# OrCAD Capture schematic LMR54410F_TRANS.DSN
size D; title: LMR54410F, SIMPLE SWITCHER® 4-V to 36-V,; rev: 1.0; note: Datasheet: SLUSEG8       EVM:SLUUCK7; note: Synchronous Step Down Converter; note: 1-A Buck Converter in SOT-23-6
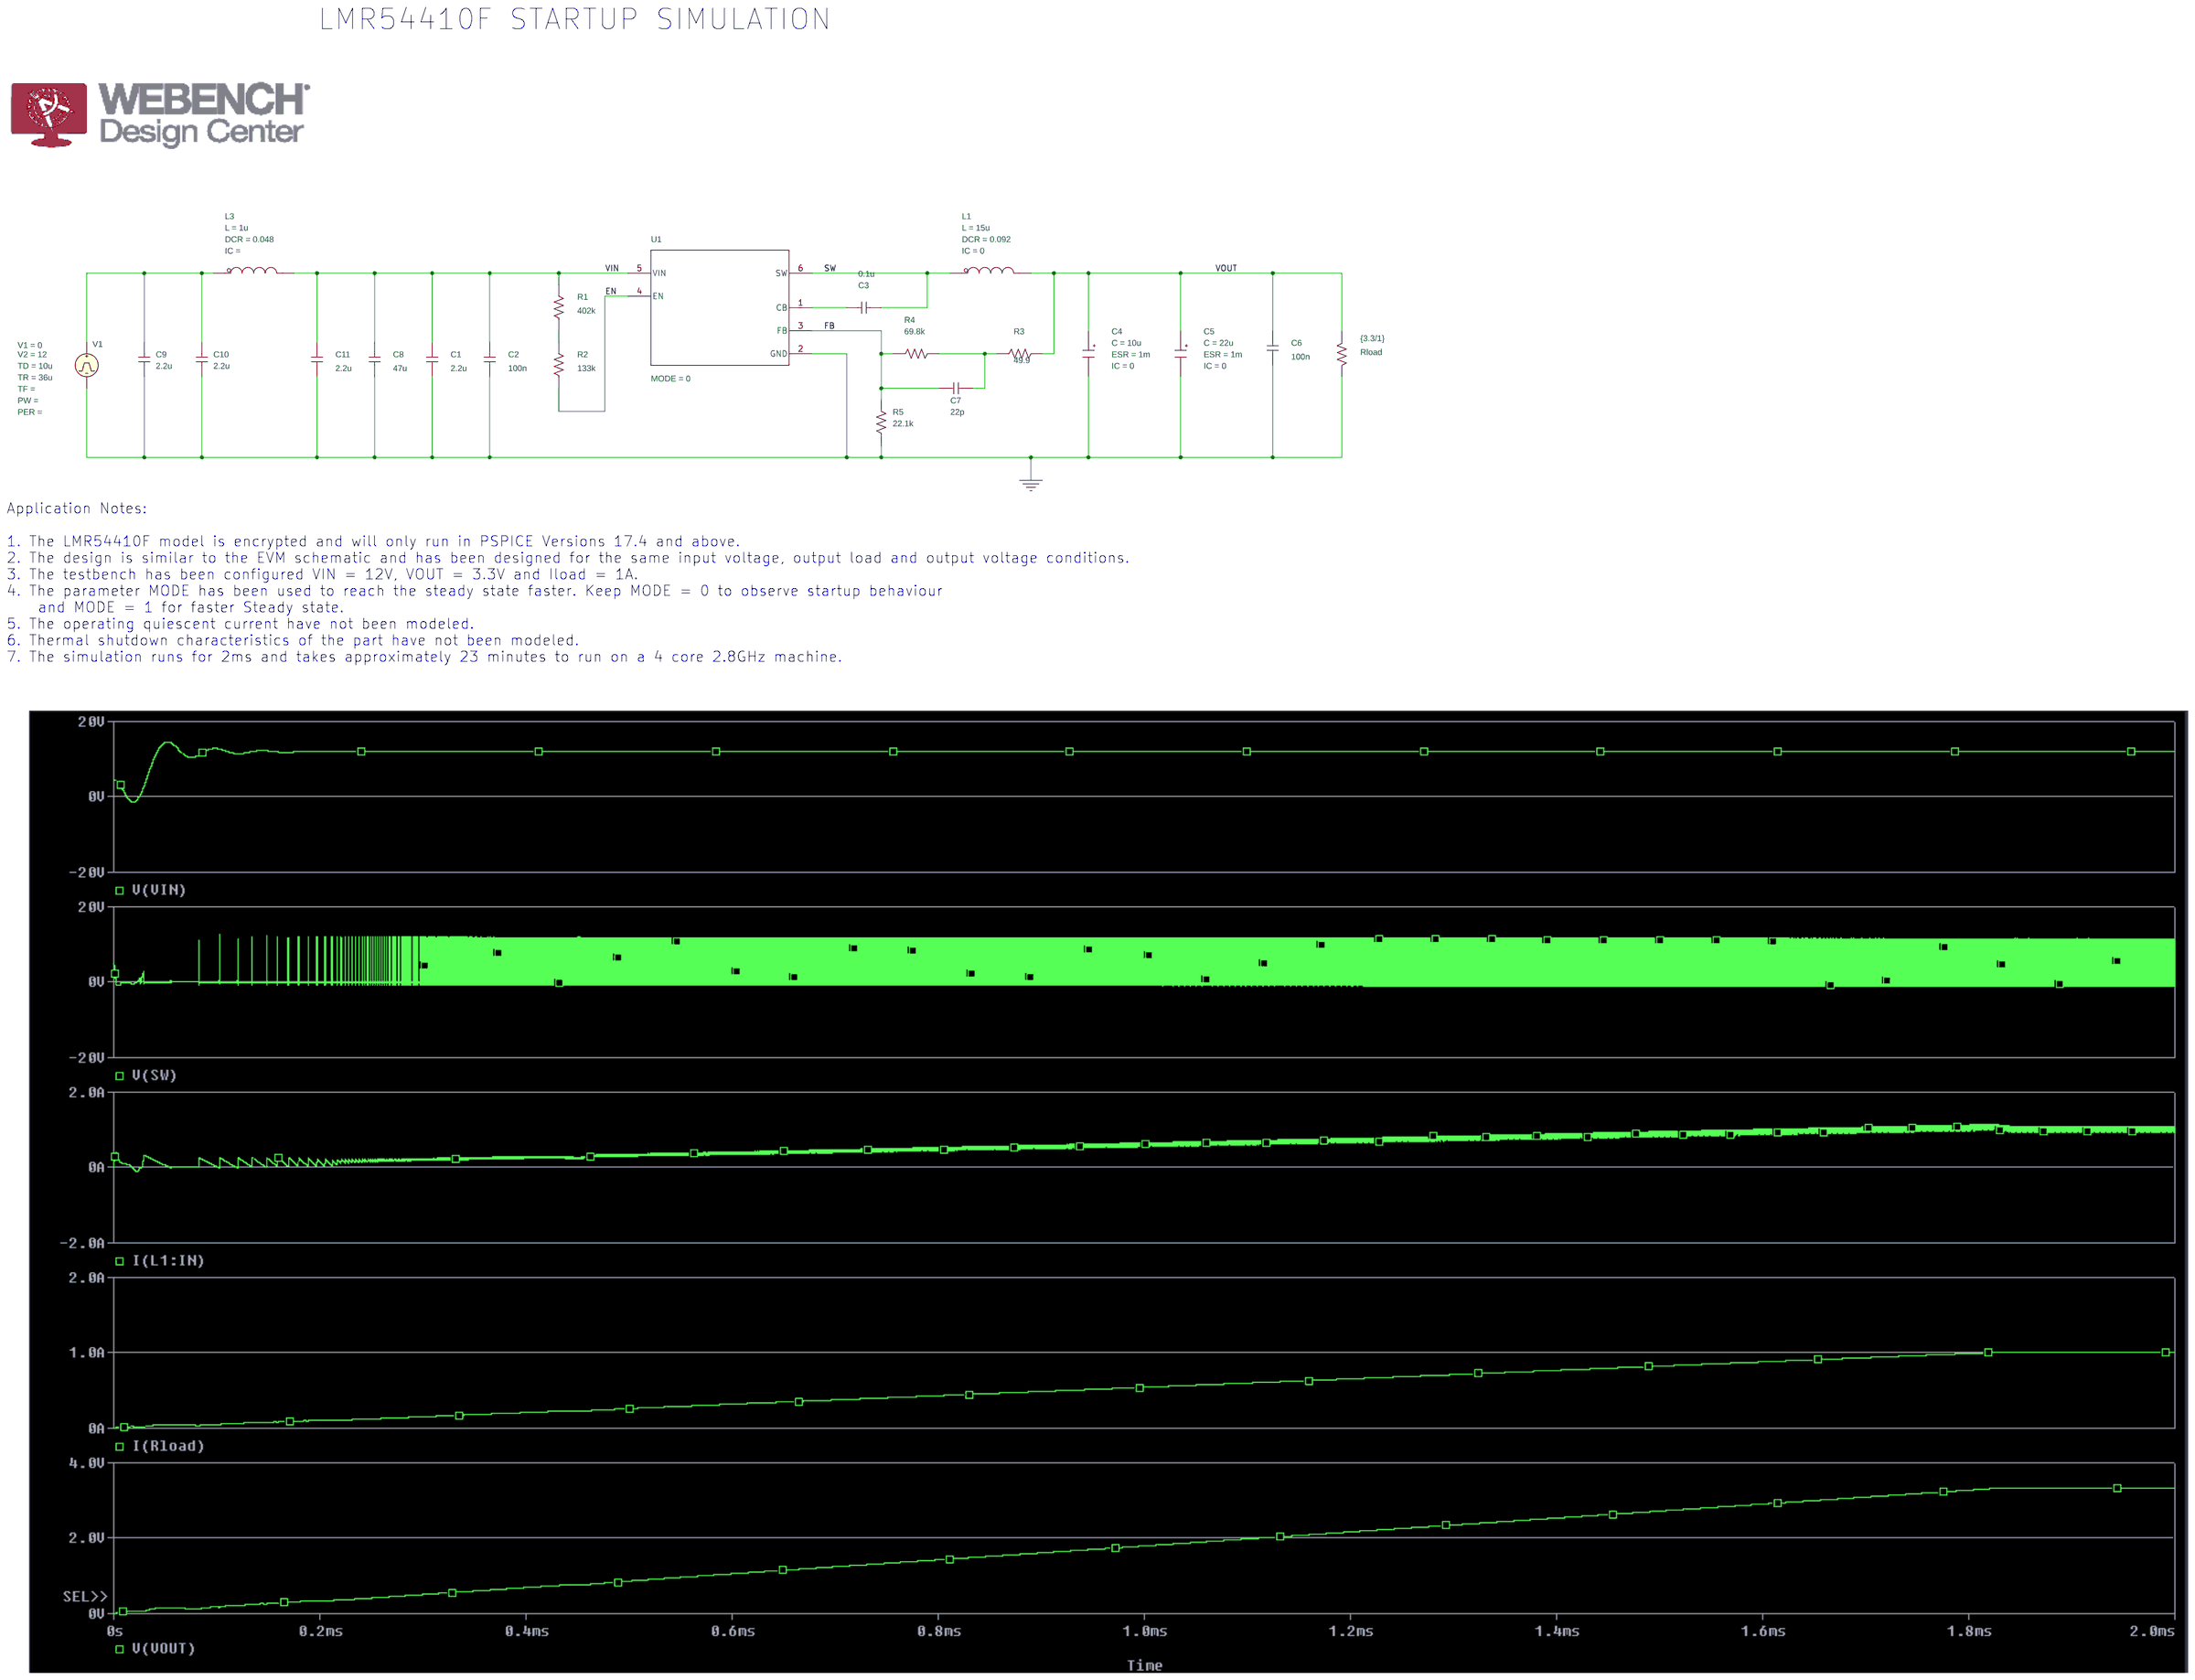
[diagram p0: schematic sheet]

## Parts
C1  2.2u  [RAD/CK05]
C2  100n  [RAD/CK05]
C3  0.1u  [RAD/CK05]
C4  CESR
C5  CESR
C6  100n  [RAD/CK05]
C7  22p  [RAD/CK05]
C8  47u  [RAD/CK05]
C9  2.2u  [RAD/CK05]
C10  2.2u  [RAD/CK05]
C11  2.2u  [RAD/CK05]
L1  LDCR
L3  LDCR
R1  402k  [AX/RC05]
R2  133k  [AX/RC05]
R3  49.9  [AX/RC05]
R4  69.8k  [RC05]
R5  22.1k  [RC05]
Rload  {3.3/1}  [AX/RC05]
U1  Value  [DBV0006A-IPC_A]
V1  VPULSE

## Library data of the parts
C1 C2 C6 C8-C11 = C
C3 = C: IC: 0
C4 = CESR_0: C: 10u; ESR: 1m; IC: 0; PSpiceTemplate: X^@REFDES %IN %OUT @MODEL PARAMS:  ?C|C=@C||C=100u|  ?ESR|ESR=@ESR||ESR=0.01| ?X|X=@X||X=2|  ?IC|IC=@IC||IC=2|; X: 1
C5 = CESR_0: C: 22u; ESR: 1m; IC: 0; PSpiceTemplate: X^@REFDES %IN %OUT @MODEL PARAMS:  ?C|C=@C||C=100u|  ?ESR|ESR=@ESR||ESR=0.01| ?X|X=@X||X=2|  ?IC|IC=@IC||IC=2|; X: 1
C7 = C: IC: 3.3
L1 = LDCR_0: DCR: 0.092; IC: 0; L: 15u; PSpiceTemplate: X^@REFDES %IN %OUT @MODEL PARAMS:  ?L|L=@L||L=1u|  ?DCR|DCR=@DCR||DCR=0.01| ?IC|IC=@IC||IC=0|
L3 = LDCR_0: DCR: 0.048; L: 1u; PSpiceTemplate: X^@REFDES %IN %OUT @MODEL PARAMS:  ?L|L=@L||L=1u|  ?DCR|DCR=@DCR||DCR=0.01| ?IC|IC=@IC||IC=0|
R1-R5 Rload = R
U1 = LMR54410FDBV_TRANS: MODE: 0
V1 = VPULSE: TD: 10u; TR: 36u; V1: 0; V2: 12

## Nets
VIN: C1.2 C2.2 C8.2 C11.2 L3.3(OUT) R1.2 U1.5(VIN)
0: C1.1 C2.1 C4.3(OUT) C5.3(OUT) C6.1 C8.1 C9.1 C10.1 C11.1 R5.1 Rload.2 U1.2(GND) V1.2(-)
EN: R2.1 U1.4(EN)
FB: C7.1 R4.1 R5.2 U1.3(FB)
SW: C3.2 L1.1(IN) U1.6(SW)
VOUT: C4.1(IN) C5.1(IN) C6.2 L1.3(OUT) R3.2 Rload.1
N16777693: C9.2 C10.2 L3.1(IN) V1.1(+)
N16777788: C3.1 U1.1(CB)
N16777793: R1.1 R2.2
N16777966: C7.2 R3.1 R4.2

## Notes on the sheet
- LMR54410F STARTUP SIMULATION
- Application Notes:
  1. The LMR54410F model is encrypted and will only run in PSPICE Versions 17.4 and above.
  2. The design is similar to the EVM schematic and has been designed for the same input voltage, output load and output voltage conditions.
  3. The testbench has been configured VIN = 12V, VOUT = 3.3V and Iload = 1A.
  4. The parameter MODE has been used to reach the steady state faster. Keep MODE = 0 to observe startup behaviour
      and MODE = 1 for faster Steady state.
  5. The operating quiescent current have not been modeled.
  6. Thermal shutdown characteristics of the part have not been modeled.
  7. The simulation runs for 2ms and takes approximately 23 minutes to run on a 4 core 2.8GHz machine.
